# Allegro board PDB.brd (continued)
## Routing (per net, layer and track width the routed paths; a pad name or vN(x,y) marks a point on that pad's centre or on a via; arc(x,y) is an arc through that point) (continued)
PSU2_CPLD_PS_ON_N: length 194.6
  TOP w0.216: v1(152.27,91.38) 153.17,90.48 166.54,90.48 167.06,91 183.21,91 184.55,89.66 R59.2 184.55,87.9 CON1.1 ; L20.2 C25.1 17.89,111.37 19.53,113.02 102.13,113.02 v1(104.65,110.5)
  BOTTOM w0.216: v1(104.65,110.5) 105.16,110.5 110.49,105.17 110.49,104.66 111.99,103.16 111.99,101.92 111.66,101.59 111.66,100.26 111.43,100.03 111.43,97.78 111.48,97.73 111.48,97.71 115.13,94.07 115.13,89.32 119.17,85.28 136.69,85.28 137.59,86.18 144.72,86.18 147.56,89.03 149.92,89.03 v1(152.27,91.38)
PSU2_CPLD_PS_ON_R_N: length 30.9
  TOP w0.216: L20.1 17.53,105.76 13.17,101.4 1.82,101.4 1.42,101.01 1.42,95.75 1.65,95.52 3.22,95.52 J9.6
PSU2_GREEN_LED: length 64.6
  TOP w0.216: J6.12 64.52,26.63 64.52,28.21 63.73,28.99 R34.1 ; Q21.5 34.21,6.09 34.57,5.73 36.2,5.73 37.16,4.77 37.16,4 37.24,3.93 v1(37.24,3.88)
  BOTTOM w0.216: v1(37.24,3.88) 37.12,3.76 37.12,3.24 38.12,2.24 46.8,2.24 50.42,5.86 66.04,5.86 68.63,8.45 68.63,21.17 65.66,24.14 65.66,25.49 J6.12
PSU2_GREEN_LED_N: length 19.7
  TOP w0.216: R178.2 v1(24.66,5) 21.31,5 17.95,8.35 17.95,11.34 18.45,11.84 C151.1 L25.2
PSU2_GREEN_LED_R1_N: length 15.6
  TOP w0.216: L25.1 18.54,14.24 12.06,20.72 8.2,20.72 J10.6
PSU2_GREEN_LED_R_N: length 4
  TOP w0.216: R178.1 32.15,4.36 32.55,3.96 34.67,3.96 34.86,4.15 Q21.3
PSU2_PRESENT_N: length 170.9
  TOP w0.216: R66.1 v1(15.85,93.97)
  VCC1 w0.213: v1(15.85,93.97) 15.11,93.23 15.11,91.2 13.89,89.98 13.89,88.1 13.28,87.49 13.28,81.82 9.71,78.25 9.71,73.1 5.46,68.85 5.46,63.95 v1(6.15,63.26) ; J6.6 71.59,25.63 72.44,26.48 72.44,28.03 71.75,28.72 69.22,28.72 68.58,28.08 68.58,23.87 64.85,20.13 64.85,13.25 62.48,10.89 60.52,10.89 57.45,7.81 22.53,7.81 22,8.34 17.49,12.85 17.49,15.46 17.49,15.95 11.24,22.2 9.43,22.2 8.51,23.13 v1(8.51,23.43)
  BOTTOM w0.216: v1(6.15,63.26) 5.31,63.26 4.28,62.23 4.28,25.53 6.38,23.43 v1(8.51,23.43)
PSU2_PS_ON_BUF_N: length 91.8
  TOP w0.216: v1(106.3,107.08) 106.44,106.94 U1.4 ; U13.2 176.43,87.23 174.64,89.03 153.58,89.03 v1(152.55,90.06)
  BOTTOM w0.216: v1(152.55,90.06) 151.86,90.06 150.41,88.61 147.74,88.61 144.89,85.77 137.79,85.77 136.89,84.86 118.99,84.86 114.71,89.15 114.71,93.39 108.97,99.13 108.97,104.66 106.55,107.08 v1(106.3,107.08) 106.17,107.2 R107.2
PSU2_PS_ON_N: length 370
  TOP w0.216: R70.2 68.44,29.76 68.44,26.29 67.78,25.63 J6.10 ; R75.2 171.28,88.06 171.15,88.19 152.49,88.19 152,88.68 v1(151.99,88.68)
  VCC1 w0.213: v1(7.06,67.45) 7.49,67.45 10.96,70.92 10.96,76.61 15.96,81.6 16.81,81.6 17.32,82.1 17.32,87.65 18.8,89.13 18.8,91.53 20.95,93.68 20.95,101.68 24.26,104.99 68.02,104.99 69.22,106.19 75.23,106.19 76.89,104.53 79.7,104.53 84.5,99.73 95.75,99.73 96.49,100.47 96.49,102.88 97.69,104.08 99.36,104.08 v1(101.73,106.44)
  BOTTOM w0.216: v1(7.06,67.45) 6.55,67.96 4.65,67.96 1.77,65.08 1.77,24.49 5.93,20.32 11.16,20.32 20.12,11.36 20.12,9.06 23.6,5.58 30,5.58 34.18,1.4 47.15,1.4 50.77,5.02 66.39,5.02 69.47,8.1 69.47,21.52 67.52,23.47 J6.10 ; v1(151.99,88.68) 151.99,88.69 151.08,87.77 148.08,87.77 145.24,84.93 138.14,84.93 137.24,84.03 118.99,84.03 118.65,84.02 113.87,88.8 113.87,93.04 108.13,98.78 108.13,103.6 106.07,105.65 102.51,105.65 v1(101.73,106.44)
PSU2_PS_ON_R_N: length 4.5
  TOP w0.216: U13.7 172.4,87.23 R75.1 172.08,87.23 171.83,86.98 170.46,86.98 v3(169.93,87.52)
PSU2_VSENSE_DN: length 20.9
  BOTTOM w0.254: R194.1 82.77,99.3 C112.2 83.09,98.99 84.46,98.99 86.44,100.96 86.44,102.53 88.26,104.36 96.76,104.36 97.66,105.25 97.66,106.02 97.24,106.44 J21.4
PSU2_VSENSE_DP: length 23.6
  BOTTOM w0.254: R193.1 82.77,98.29 C112.1 83.09,98.6 84.62,98.6 86.82,100.8 86.82,102.38 88.42,103.98 96.92,103.98 98.04,105.09 98.04,106.84 97.1,107.78 J21.3
PSU2_YELLOW_LED: length 66.7
  TOP w0.216: v1(36.51,3.81) 36.68,3.98 36.68,4.66 36.03,5.31 34.48,5.31 34.21,5.04 Q21.2 ; J6.13 62.76,28.39 R31.1
  BOTTOM w0.216: J6.13 63.52,27.63 64.52,26.63 65.84,26.63 66.44,26.03 66.44,23.95 69.05,21.35 69.05,8.27 66.21,5.44 50.59,5.44 46.97,1.82 37.95,1.82 36.7,3.06 36.7,3.62 v1(36.51,3.81)
PSU2_YELLOW_LED_N: length 18.8
  TOP w0.216: L22.1 C148.1 19.61,11.84 20.07,11.38 20.07,9.95 19.41,9.29 19.41,7.51 21.23,5.68 v1(22.61,5.68) 31.02,5.68 R175.1
PSU2_YELLOW_LED_R1_N: length 20.6
  TOP w0.216: J10.5 5.8,18.15 5.8,20.21 6.72,21.13 12.24,21.13 19.56,13.82 L22.2
PSU2_YELLOW_LED_R_N: length 1.6
  TOP w0.216: Q21.6 33.12,6.01 R175.2
PSU3_ALERT_BUF_N: length 2.9
  TOP w0.216: v1(112.55,1.54) 112.42,1.67 R187.1
  BOTTOM w0.216: U23.4 113.25,2.82 112.55,2.12 v1(112.55,1.54)
PSU3_ALERT_N: length 28.4
  TOP w0.216: J7.11 91.7,1.28 109.22,1.28 109.78,1.84 110.18,1.84 v1(110.21,1.88) 110.3,1.88 110.75,2.33 112.84,2.33 113.39,1.78 R64.2
  BOTTOM w0.216: v1(110.21,1.88) 110.51,2.17 U23.2
PSU3_BLADE_EN_N: length 30.7
  TOP w0.216: J7.1 75.82,4.46 74.73,5.55 64.21,5.55 61.7,3.04 R74.1
PSU3_BLADE_EN_R_N: length 249.5
  TOP w0.216: U1.14 111.85,102.39 111.48,102.75 v1(111.47,102.75) ; R74.2 C30.1 48.57,4.78 v1(47.98,5.37)
  VCC1 w0.213: v1(106.35,108.4) 105.09,107.14 104.1,107.14 100.2,103.25 98.12,103.25 97.33,102.45 97.33,100.13 96.1,98.9 84.15,98.9 79.35,103.7 72.82,103.7 72.36,104.16 70.01,104.16 70,104.15 24.6,104.15 22.99,102.54 22.99,90.18 21.79,88.99 21.79,82.67 19.86,80.74 16.27,80.74 11.8,76.26 11.8,69.72 7.87,65.8 v1(7.06,65.8)
  BOTTOM w0.216: v1(106.35,108.4) 106.41,108.46 106.59,108.46 110.03,105.02 110.03,104.51 111.47,103.07 v1(111.47,102.75) 111.47,102.11 R112.2 ; v1(7.06,65.8) 5.31,65.8 3.02,63.51 3.02,25.01 6.46,21.58 11.68,21.58 22.36,10.89 22.36,8.59 24.05,6.9 46.84,6.9 47.98,5.76 v1(47.98,5.37)
PSU3_GREEN_LED: length 63.5
  TOP w0.216: Q22.5 27.66,2.12 27.99,2.45 38,2.45 40.39,4.84 45.47,4.84 45.87,5.24 R35.1 46.4,6.01 75.41,6.01 75.95,5.48 87.54,5.48 J7.12
PSU3_GREEN_LED_N: length 14.6
  TOP w0.216: L26.2 C150.1 17.07,11.84 17.53,11.38 17.53,8.18 22.5,3.22 v1(23.34,3.22) R179.2
PSU3_GREEN_LED_R1_N: length 11.4
  TOP w0.216: L26.1 17.02,15.17 13.5,18.68 9.26,18.68 J10.8
PSU3_GREEN_LED_R_N: length 1.4
  TOP w0.216: Q22.3 26.96,3.83 v1(26.41,3.83) 26.41,3.83 25.9,3.32 R179.1
PSU3_PRESENT_N: length 164.8
  TOP w0.216: v1(62.28,7.26) 65.03,7.26 65.15,7.38 82.08,7.38 82.53,6.93 J7.6 ; R67.1 v1(16.86,93.87)
  VCC1 w0.213: v1(6.6,64.66) 6.32,64.94 6.32,67.81 10.55,72.03 10.55,76.93 15.16,81.54 15.16,85.24 15.07,85.32 15.07,89.89 16.38,91.2 16.38,93.38 v1(16.86,93.87)
  BOTTOM w0.216: v1(6.6,64.66) 4.93,64.66 3.44,63.17 3.44,25.18 6.63,22 11.86,22 22.78,11.07 22.78,8.76 24.23,7.32 62.22,7.32 v1(62.28,7.26)
PSU3_PS_ON_BUF_N: length 86.5
  TOP w0.216: U1.5 v1(106.3,106.29) ; v1(152.53,89.19) 153.11,88.61 171.33,88.61 171.4,88.53 U13.5
  BOTTOM w0.216: v1(152.53,89.19) 151.59,89.19 150.58,88.19 147.91,88.19 145.06,85.35 137.97,85.35 137.07,84.44 118.82,84.44 114.29,88.98 114.29,93.21 108.55,98.95 108.55,104.04 v1(106.3,106.29) 106.2,106.19 R108.2
PSU3_PS_ON_N: length 189.3
  TOP w0.216: R76.2 178.06,89.45 153.9,89.45 v1(153.39,89.96) ; J7.10 88.03,7.96 R71.2 97.43,9.54 99.24,7.74 102.41,7.74 v1(102.57,7.58)
  BOTTOM w0.216: v1(153.39,89.96) 153.39,88.81 151.76,87.19 148.24,87.19 145.56,84.51 138.62,84.51 136.96,82.84 136.96,74.34 150.81,60.48 150.81,38.96 150.77,38.86 150.73,38.65 150.73,38.45 150.77,38.24 150.77,36.03 148.99,34.25 148.16,34.25 147.19,33.29 145.84,33.29 145.15,32.6 140.75,32.6 138.16,35.19 127.17,35.19 122.14,30.16 122.14,26.82 120.78,25.47 120.78,18.11 119.53,16.86 116.03,16.86 114.57,15.4 107.74,15.4 106.01,13.66 106.01,7.93 105.66,7.58 v1(102.57,7.58)
PSU3_PS_ON_R_N: length 3.5
  TOP w0.216: v3(180.34,89.04) 179.22,87.92 R76.1 178.75,87.88 U13.3
PSU3_VSENSE_DN: length 17.1
  BOTTOM w0.254: J21.6 94.29,107.25 89.96,107.25 85.67,102.96 85.67,101.82 84.72,100.87 83.12,100.87 C113.2 82.65,100.4 R196.1
PSU3_VSENSE_DP: length 17
  BOTTOM w0.254: J21.5 94.29,107.63 89.8,107.63 85.29,103.12 85.29,101.98 84.56,101.25 83.06,101.25 C113.1 82.77,101.54 R195.1
PSU3_YELLOW_LED: length 66.5
  TOP w0.216: v1(75.82,6.49) R32.1 45.87,6.73 45.47,7.13 42.04,7.13 37.78,2.87 28.17,2.87 27.66,3.38 Q22.2
  BOTTOM w0.216: J7.13 90.42,4.46 89.41,5.48 76.83,5.48 v1(75.82,6.49)
PSU3_YELLOW_LED_N: length 16.4
  TOP w0.216: R176.1 v1(24.31,2.2) 22.92,2.2 15.44,9.67 15.44,11.6 15.69,11.84 C149.1 L23.1
PSU3_YELLOW_LED_R1_N: length 10.6
  TOP w0.216: J10.7 9.66,18.18 13.42,18.18 16,15.59 L23.2
PSU3_YELLOW_LED_R_N: length 4
  TOP w0.216: Q22.6 28.32,1.87 28.32,1.28 28.12,1.08 26.24,1.08 v1(25.9,1.42) R176.2
PSU_ALERT_N: length 228.1
  TOP w0.216: v1(39.88,2.94) 41.02,1.79 69.47,1.79 69.74,2.07 R186.2 72.56,2.55 74.24,0.87 109.39,0.87 109.89,1.36 110.67,1.36 R187.2 ; R68.2 27.99,110.89 25.91,108.8 22.25,108.8 21.82,109.23 C133.1 L10.1 20.85,106.58 15.83,101.56 15.83,97.33 10.89,92.4 R188.2 ; R188.2 10.13,92.01 9.79,91.66 9.79,90.36 9.79,90.05 9.63,89.89 C130.1 v1(9.27,89.28) L5.1 ; R188.2 C116.1
  VCC1 w0.213: v1(4.93,67.17) 5.04,67.29 5.04,69.02 9.3,73.27 9.3,79.06 11.16,80.92 11.16,86.42 9.27,88.31 v1(9.27,89.28)
  BOTTOM w0.216: v1(4.93,67.17) 4.72,67.17 2.18,64.63 2.18,24.66 6.11,20.74 11.34,20.74 20.54,11.54 20.54,9.23 23.77,6 33.07,6 33.63,5.44 37.38,5.44 v1(39.88,2.94)
PSU_ALERT_R_N: length 3.3
  TOP w0.216: J8.11 10.24,85.89 9.27,86.86 L5.2
PSU_PRESENT_N: length 8.6
  TOP w0.216: L13.2 C144.1 14.96,90.5 14.96,92.07 15.22,92.33 R66.2 R67.2 C27.1 17.9,92.35 v1(18.65,92.34) R65.2
PSU_PRESENT_R_N: length 5.8
  TOP w0.216: L13.1 14.35,87.04 15.2,86.18 15.2,83.62 15.96,82.86 J8.6
PSU_PS_ON_AND_N: length 12.1
  TOP w0.216: CON1.2 182.35,85.76 180.72,87.39 v3(180.21,87.39) 180.09,87.39 179.26,86.56 R60.2 178.77,86.58 U13.1 175.57,86.58 174.27,87.88 U13.6
PSU_PS_ON_N: length 218
  TOP w0.216: R70.1 66.78,28.82 66.6,28.64 66.6,23.51 65.46,22.37 v1(65.15,22.37) ; L15.2 v1(10.54,89.2) C141.1 10.78,89.89 11.1,90.22 11.1,92.01 16.24,97.16 16.24,101.38 22.98,108.12 29,108.12 29.48,107.63 C29.1 R69.1 ; v1(63.88,7.89) 85.58,7.89 R71.1
  VCC1 w0.213: v1(10.59,78.22) 10.13,77.76 10.13,72.63 5.92,68.42 5.92,67.99 5.91,67.98 5.91,64.76 5.92,64.75 5.92,64.3 v1(6.17,64.05)
  BOTTOM w0.216: v1(10.54,89.2) 11.2,88.54 11.2,78.86 10.59,78.25 v1(10.59,78.22) ; v1(65.15,22.37) 65.01,22.23 65.01,8.02 64.89,7.89 v1(63.88,7.89) 62.09,7.89 61.94,7.74 24.4,7.74 23.27,8.87 23.27,11.18 12.03,22.41 6.8,22.41 3.86,25.36 3.86,62.7 5.21,64.05 v1(6.17,64.05)
PSU_PS_ON_R1_N: length 5.6
  TOP w0.216: J8.10 11.2,83.9 11.2,86.83 10.54,87.49 L15.1
PSU_VSENSE_DN: length 111.9
  TOP w0.254: R192.2 80.75,100.73 78.97,100.73 v1(78.72,100.48) 78.42,100.78 77.9,100.78 77.14,101.54 72.24,101.54 69.85,103.93 24.72,103.93 23.37,102.57 23.37,90.21 22.89,89.73 22.89,62.46 23.72,61.62 SHORT2.1
  VCC1 w0.254: v1(78.72,100.48) 79.02,100.78 80.18,100.78 80.7,100.26 80.7,99.18 80.47,98.96 80.04,98.96 v1(79.73,99.26)
  BOTTOM w0.254: R192.2 80.75,100.73 78.97,100.73 v1(78.72,100.48) ; v1(79.73,99.26) 80.01,98.99 80.77,98.99 R194.2
PSU_VSENSE_DP: length 114.7
  TOP w0.254: SHORT1.1 23.64,61.17 22.5,62.3 22.5,89.89 22.99,90.37 22.99,102.73 24.56,104.31 70.01,104.31 72.4,101.92 77.3,101.92 78.06,101.16 78.42,101.16 v1(78.72,101.46) 79.07,101.11 80.65,101.11 R191.2
  VCC1 w0.254: v1(79.73,98.28) 80.04,98.58 80.63,98.58 81.08,99.02 81.08,100.42 80.34,101.16 79.02,101.16 v1(78.72,101.46)
  BOTTOM w0.254: v1(78.72,101.46) 79.07,101.11 80.65,101.11 R191.2 ; v1(79.73,98.28) 80.06,98.6 80.77,98.6 R193.2
PU_I2C_PCA9546A_2_SCL: length 4.2
  TOP w0.216: v1(78.49,110) 77.83,109.34 U14.10
  BOTTOM w0.216: v1(78.49,110) 78.54,110 79.43,109.11 R98.2
PU_I2C_PCA9546A_2_SDA: length 4.1
  TOP w0.216: U14.9 76.57,110.09 v1(77.22,110.73)
  BOTTOM w0.216: R97.2 79.38,110.12 78.77,110.73 v1(77.22,110.73)
PU_I2C_PCA9546A_3_SCL: length 5.3
  TOP w0.216: U14.12 77.14,108.04 77.93,107.25 77.93,106.21 v1(78,106.14)
  BOTTOM w0.216: v1(78,106.14) 78.31,106.14 79.25,107.08 R100.2
PU_I2C_PCA9546A_3_SDA: length 3.8
  TOP w0.216: v1(78.44,108.35) 77.76,108.35 77.42,108.69 U14.11
  BOTTOM w0.216: v1(78.44,108.35) 79.23,108.35 R99.2
RISER3_OC_ALERT: length 11.1
  BOTTOM w0.216: Q13.5 140.36,23.61 139.73,22.98 R130.2 R132.1 139.3,21.99 138.81,21.99 138.61,21.78 v2(138.61,18.61) 139.05,18.17 R26.1 139.05,16.84 R160.1
RISER3_OC_ALERT_N: length 2.9
  BOTTOM w0.216: v2(144.42,13.02) 144.42,14.44 Q17.6 144.73,14.75 145.3,14.75
  BOTTOM w0.254: R159.2 145.3,14.75
RISER3_OC_ALERT_R: length 4.7
  BOTTOM w0.216: Q17.5 Q17.2 v2(141.12,15.25) 140.95,15.08 R160.2
RISER3_OC_ALERT_R1_N: length 6.3
  BOTTOM w0.216: Q17.3 142.69,16.21 142.91,16.43 145.25,16.43 145.25,16.44 145.48,16.44 R170.1 145.78,15.83 146.1,15.51 147.42,15.51 v2(147.84,15.93)
RISER3_OC_ALERT_R_N: length 153.3
  TOP w0.216: U1.17 v1(114.68,104.34)
  BOTTOM w0.216: v1(114.68,104.34) 116.83,104.34 118.87,102.3 144.03,102.3 150.57,95.76 152.74,95.76 154.27,97.28 157.34,97.28 158.09,96.53 158.09,89.92 152.75,84.58 150.91,84.58 148.97,82.64 148.97,66.62 154.78,60.81 154.78,53.15 154.78,52.81 162.1,45.48 162.1,36.74 154.76,29.4 151.71,29.4 150.6,28.28 150.6,20.23 151.41,19.42 151.41,15.53 149.91,14.04 147.73,14.04 147.55,14.21 R7.2 R159.1
RISER3_OC_CLEAR: length 113
  TOP w0.216: v1(106.4,104.34) U1.8 ; v1(145.9,24.73) 145.9,31.36 146.58,32.04 146.58,33.77 146.56,33.8 v1(146.56,33.8)
  BOTTOM w0.216: Q13.2 144.77,23.61 R17.1 144.89,23.62 145.9,24.63 v1(145.9,24.73) ; v1(106.4,104.34) 106.62,104.34 107.66,103.3 107.66,98.35 106.83,97.52 106.83,92.49 117.41,81.9 117.41,76.39 123.79,70.01 137.25,70.01 146.47,60.79 146.47,52.82 150.28,49.01 150.28,36.24 148.81,34.76 148.03,34.76 147.07,33.8 v1(146.56,33.8)
RISER4_OC_ALERT: length 7.1
  BOTTOM w0.216: R162.1 131.19,49.18 131.19,50.64 v2(130.71,51.12) 130.05,51.78 R27.1 R131.2 131.3,52.19 131.72,52.61 R133.1 132.28,52.61 132.82,53.15 Q14.5
RISER4_OC_ALERT_N: length 1.5
  BOTTOM w0.216: Q18.6 v4(126.7,49.81) 126.36,49.48 R161.2
RISER4_OC_ALERT_R: length 3.1
  BOTTOM w0.216: Q18.5 128.24,49.16 v4(128.37,49.04) 128.5,49.16 Q18.2 R162.2
RISER4_OC_ALERT_R1_N: length 4
  BOTTOM w0.216: v2(129.03,46.12) 129.77,46.12 R172.1 130.09,46.75 129.35,47.49 Q18.3
RISER4_OC_ALERT_R_N: length 113.5
  TOP w0.216: v1(104.72,101.87) 104.9,101.87 105.77,101.01 108.51,101.01 108.84,101.34 108.84,102.29 110.83,104.28 111.81,104.28 112.52,104.99 U1.18
  BOTTOM w0.216: v1(104.72,101.87) 104.65,101.8 104.65,98.44 105.15,97.94 105.15,91.79 115.74,81.21 115.74,75.7 123.1,68.33 136.55,68.33 144.79,60.1 144.79,47.67 142.45,45.33 126.49,45.33 126.36,45.46 R161.1 R8.2
RISER4_OC_CLEAR: length 72.1
  TOP w0.216: v1(104.96,103.14) 105.54,103.14 106.09,103.69 U1.9
  BOTTOM w0.216: v1(104.96,103.14) 104.27,103.14 104.14,103.01 104.14,98.13 104.73,97.54 104.73,91.62 115.32,81.03 115.32,75.52 122.92,67.92 130.09,67.92 133.25,64.76 133.25,60.21 135.36,58.1 135.36,55.49 136.25,54.59 R18.1 135.92,53.15 Q14.2
RISER5_OC_ALERT: length 7.5
  BOTTOM w0.216: R2.1 139.8,89.04 v2(139.55,88.79) R28.1 R144.2 138.28,89.77 R146.1 138.15,90.57 136.7,92.01 Q15.5
RISER5_OC_ALERT_N: length 2.7
  BOTTOM w0.216: R1.2 144.93,88.86 Q1.6 v2(146.56,88.9)
RISER5_OC_ALERT_R: length 6
  BOTTOM w0.216: R2.2 142.51,89.55 Q1.2 Q1.5 145.29,89.55 145.8,90.06 145.8,91.15 v2(146.3,91.66)
RISER5_OC_ALERT_R1_N: length 4.2
  BOTTOM w0.216: Q1.3 143.07,91.34 143.64,91.91 R5.1 144.08,92.15 v2(145.21,93.28)
RISER5_OC_ALERT_R_N: length 51.6
  TOP w0.216: v1(111.3,104.89) 112.06,105.65 113.53,105.65 U1.19
  BOTTOM w0.216: R1.1 R9.2 142.01,86.93 141.68,86.6 137.41,86.6 136.51,85.7 119.34,85.7 115.54,89.5 115.54,94.24 111.9,97.88 111.9,99.91 112.08,100.09 112.08,101.42 112.41,101.75 112.41,103.79 v1(111.3,104.89)
RISER5_OC_CLEAR: length 45.2
  TOP w0.216: U1.10 108.38,103.04 109.86,104.51 v1(109.86,107.51)
  BOTTOM w0.216: v1(109.86,107.51) 112.83,104.54 112.83,101.57 112.5,101.24 112.5,99.91 112.32,99.74 112.32,98.06 112.9,97.47 118.16,97.47 120.14,99.46 125.73,99.46 130.81,94.38 133.86,94.38 134.62,95.14 135.91,95.14 R19.1 136.7,94.56 Q15.2
RST_I2C_MUX_N: length 33.7
  TOP w0.216: v1(87.71,102.43) 87,103.14 84.33,103.14 83.67,103.79 R109.2 83.12,105.06 82.83,105.35 82.83,106.36 82.45,106.74 U14.3 ; U1.7 105.86,104.99 105.05,104.18 103.89,104.18 v1(103.2,103.49)
  BOTTOM w0.216: v1(87.71,102.43) 90.78,99.35 100.84,99.35 102.26,100.78 102.26,102.55 v1(103.2,103.49)
TEMP_SENSE_1_DN: length 205.5
  TOP w0.254: v1(91.26,101.27) 91.55,101.56 U2.3 ; v1(9.45,13.76) 9.75,13.46 10.33,13.46 C38.2 11.1,14.23 Q11.2
  VCC1 w0.254: v1(91.26,101.27) 90.92,101.61 89.94,101.61 89.36,102.19 89.36,110.48 87.48,112.36 73.69,112.36 72.62,111.29 68.39,111.29 66.88,112.8 43.46,112.8 43.13,112.47 35.43,112.47 35.42,112.47 34.17,112.47 34.17,112.47 27.07,112.47 25.11,110.5 22.38,110.5 13.56,101.69 3.17,101.69 1.55,100.07 1.55,95.26 1.72,95.1 1.72,15.01 3.25,13.48 9.16,13.48 v1(9.45,13.76)
TEMP_SENSE_1_DP: length 207.1
  TOP w0.254: Q11.1 12.85,13.28 Q11.3 11.64,13.28 11.18,12.82 10.59,12.82 C38.1 10.33,13.08 9.75,13.08 v1(9.45,12.78) ; v1(91.26,102.25) 91.45,102.06 U2.2
  VCC1 w0.254: v1(9.45,12.78) 9.13,13.1 3.09,13.1 1.34,14.85 1.34,94.94 1.17,95.11 1.17,100.22 3.02,102.07 13.41,102.07 22.22,110.89 24.95,110.89 26.91,112.85 34.01,112.85 34.01,112.85 35.58,112.85 35.59,112.85 42.97,112.85 43.31,113.18 67.04,113.18 68.55,111.67 72.46,111.67 73.53,112.74 87.64,112.74 89.74,110.64 89.74,102.35 90.09,102 91,102 v1(91.26,102.25)
TEMP_SENSE_2_DN: length 102.3
  TOP w0.254: U2.5 93.92,100.56 93.98,100.62 94.25,100.62 95.93,98.95 102.46,98.95 105.63,95.77 107.32,95.77 v1(107.62,95.47) ; v1(147.7,61.28) 148,61.58 152.52,61.58 159.09,55.02 167.43,55.02 167.72,54.73 C37.2 168.58,54.73 Q10.2
  BOTTOM w0.254: v1(107.62,95.47) 108,95.85 108.74,95.85 109.27,95.32 109.27,91.45 118.41,82.31 118.41,76.81 124.21,71.01 137.66,71.01 147.07,61.6 147.39,61.6 v1(147.7,61.28)
TEMP_SENSE_2_DP: length 104.2
  TOP w0.254: U2.4 93.92,101.06 93.98,101 94.41,101 96.09,99.33 102.62,99.33 105.79,96.15 107.32,96.15 v1(107.62,96.45) ; v1(147.7,62.27) 148,61.97 152.68,61.97 159.25,55.4 167.59,55.4 167.72,55.53 C37.1 169.39,55.53 Q10.1 170.59,55.68 Q10.3
  BOTTOM w0.254: v1(107.62,96.45) 107.84,96.23 108.9,96.23 109.65,95.47 109.65,91.61 118.79,82.47 118.79,76.96 124.36,71.39 137.82,71.39 147.23,61.98 147.41,61.98 v1(147.7,62.27)
UNNAMED_9_AT24C64D_I33_WP: length 5.8
  TOP w0.216: v3(157.23,93.5) 157.86,92.87 160.25,92.87 160.52,93.14 R117.1 U3.7
UNNAMED_10_RES_I2_A: length 3.3
  BOTTOM w0.216: R136.1 145.23,17.8 144.92,17.49 v2(144.81,17.49) 144.61,17.49 143.87,18.24 U5.3
UNNAMED_10_RES_I18_B: length 3.1
  BOTTOM w0.216: R132.2 139.32,20.08 v2(139.45,19.95) 139.86,19.54 U5.6
UNNAMED_10_RES_I30_A: length 2.1
  BOTTOM w0.216: R137.1 135.96,47.44 v4(135.59,47.44) 135.24,47.78 U7.3
UNNAMED_10_RES_I40_B: length 3.5
  BOTTOM w0.216: R133.2 v2(132.08,50.56) 132.08,50.43 131.7,50.05 131.7,49.29 131.91,49.08 U7.6
UNNAMED_11_RES_I2_A: length 3.9
  BOTTOM w0.216: v2(143.61,96.51) 142.98,95.89 R150.1 142.08,95.84 U9.3
UNNAMED_11_RES_I13_B: length 6.3
  BOTTOM w0.216: R146.2 139.08,90.58 140.05,91.55 U9.6 140.78,91.92 141.17,92.32 142.24,92.32 143.74,93.82 v2(143.84,93.82)
UNNAMED_11_RES_I20_A: length 3.1
  BOTTOM w0.216: R151.1 181.08,84.47 v2(180.09,84.47) 180.09,84.06 180.76,83.39 U11.3
UNNAMED_11_RES_I26_B: length 4.9
  BOTTOM w0.216: U11.6 183.97,82.01 184.09,81.87 184.09,81.21 184.3,80.99 185.37,80.99 185.5,81.12 185.75,81.12 v2(185.83,81.04) 185.83,80.42 R147.2
UNNAMED_12_NPN_I60_B: length 43
  TOP w0.216: v1(105.6,27.51) 106.09,27.51 PR1047.2
  BOTTOM w0.254: v1(105.6,27.51) 105.17,27.51 104.22,28.46 104.22,29.45 98.76,34.91 97.14,34.91 93.55,38.51 93.55,56.17 v2(93.95,56.58) 94.36,56.99 PQ109.3 94.36,61.91 PQ109.1
UNNAMED_12_NPN_I60_E: length 41.9
  TOP w0.216: v1(105.61,28.23) 106.23,28.23 PR1046.2
  BOTTOM w0.254: v1(105.61,28.23) 105.11,28.23 104.67,28.67 104.67,29.64 98.94,35.37 97.33,35.37 94.01,38.7 94.01,55.69 94.82,56.5 94.82,59.53 95.25,59.96 95.25,62.8 PQ109.2
UNNAMED_19_CAP_I128_A: length 1.5
  TOP w0.381: PR27.2 173.81,34.45 v1(174.29,34.94) 173.81,35.43 PC28.1
UNNAMED_23_CAP_I5_A: length 1.4
  TOP w0.508: C166.1 R234.2
UNNAMED_23_CAP_I8_A: length 1.3
  BOTTOM w0.508: R236.2 C168.1
UNNAMED_23_CAP_I12_A: length 1.6
  BOTTOM w0.508: R238.2 27.25,66.27 C170.1
UNNAMED_23_CAP_I17_A: length 1.8
  TOP w0.508: R244.2 v1(130.84,100.6) C176.1
UNNAMED_23_CAP_I20_A: length 1.5
  BOTTOM w0.508: C174.1 176.08,72.15 R242.2
UNNAMED_23_CAP_I24_A: length 1.4
  BOTTOM w0.381: R240.2 54.21,24.02 C172.1
UNNAMED_23_CAP_I32_A: length 1.8
  TOP w0.381: C175.1 v1(144.83,75.96) R243.2
UNNAMED_23_CAP_I40_A: length 1.3
  TOP w0.381: R239.2 C171.1
UNNAMED_23_CAP_I48_A: length 1.3
  BOTTOM w0.508: C167.1 R235.2
UNNAMED_23_CAP_I52_A: length 1.8
  TOP w0.381: C178.1 176.99,48.34 v1(177.62,48.34)
  TOP w0.508: v1(177.62,48.34) R57.2
UNNAMED_23_CAP_I56_A: length 1.5
  BOTTOM w0.381: R221.2 155.39,14.49 C191.1
UNNAMED_23_CAP_I60_A: length 1.5
  TOP w0.381: R222.2 160.23,53.16 C192.1
UNNAMED_23_CAP_I64_A: length 2
  TOP w0.508: R223.2 168.97,85.23 v1(169.65,85.23) C193.1
UNNAMED_214_ADM1172_I37_SENSE: length 3.5
  TOP w0.254: R155.2 105.15,9.44 105.31,9.29 v1(105.31,8.9) 105.31,8.73 105.03,8.45 C110.2 104.5,8.23 U20.7
UNNAMED_214_ADM1172_I37_VCC: length 5.6
  TOP w0.254: U20.8 103.85,7.56 103.72,7.69 103.25,7.69 102.39,8.55 C108.1 103.05,8.83 v1(103.25,8.63) 103.43,8.45 C110.1 103.92,9.34 R154.2
UNNAMED_214_CAP_I27_A: length 3.3
  TOP w0.381: C105.1 115.62,3.49 115.37,3.24 v1(114.96,3.24) 114.48,3.72 R50.2
VR_P3V3_CB_BT: length 2.5
  TOP w0.254: PU113.14 168.99,104.98 v1(168.83,104.83)
  BOTTOM w0.508: PC1828.1 168.43,105.23 v1(168.83,104.83)
VR_P3V3_CB_PVIN:
  vias: v1(162.69,101.61) v1(163.7,101.49) v1(164.59,101.5) v1(164.97,102.34) v1(165.33,104.5) v1(165.38,101.35) v1(165.68,105.92) v1(166.34,104.52) v2(161.14,102.15)
VR_P3V3_CB_SW: length 1.5
  BOTTOM w0.508: v1(166.95,108) 167.54,107.41 PC1828.2
VR_P3V3_STBY_BT: length 3.5
  TOP w0.254: v1(161.35,21.09) 161.2,20.94 PU33.14
  BOTTOM w0.381: v1(161.35,21.09) 161.09,20.83 v2(161.09,20.31) 162.1,20.31 PC828.1
VR_P3V3_STBY_PVIN: length 11.9
  VCC1 w0.305: v1(161.75,15.58) 161.93,15.76 161.93,19.83 162.56,20.46 162.56,22.16 163.17,22.77 167.02,22.77 v1(167.22,22.97)
  vias: v1(163.71,21.83) v1(163.79,24.37) v1(164.04,21.14) v1(164.58,20.05) v1(164.98,20.96)
VR_P3V3_STBY_SW: length 1.6
  BOTTOM w0.508: PC828.2 162.48,18.67 v1(163.24,17.92)

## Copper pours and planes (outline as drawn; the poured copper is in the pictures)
GND on TOP (solid shape): 22.99,16.78 22.99,15.51 22.73,15.25 21.21,15.25 18.8,17.67 18.8,19.06 19.18,19.45 20.32,19.45
GND on TOP (solid shape): 27.69,78.75 27.69,76.6 27.3,76.21 24.51,76.21 24.26,76.47 24.26,78.88 24.51,79.14 27.3,79.14
GND on TOP (solid shape): 27.69,71.64 27.69,69.48 27.3,69.1 24.51,69.1 24.26,69.36 24.26,71.77 24.51,72.02 27.3,72.02
GND on TOP (solid shape): 52.7,27.45 52.7,25.41 52.58,25.29 48.9,25.29 48.51,25.67 48.51,27.19 48.9,27.57 52.58,27.57
GND on TOP (solid shape): 54.1,66.82 54.1,64.66 53.72,64.28 50.04,64.28 49.66,64.66 49.66,67.07 49.91,67.32 53.59,67.32
GND on TOP (solid shape): 62.61,90.57 62.61,87.14 62.1,86.63 60.71,86.63 60.45,86.88 60.45,90.57 60.83,90.95 62.23,90.95
GND on TOP (solid shape): 72.14,90.57 72.14,87.14 71.63,86.63 70.23,86.63 69.98,86.88 69.98,90.57 70.36,90.95 71.75,90.95
GND on TOP (solid shape): 74.93,48.78 74.93,46.5 74.42,45.99 62.48,45.99 61.98,46.5 61.98,48.78 62.48,49.29 74.42,49.29
GND on TOP (solid shape): 75.18,66.82 75.18,64.66 74.8,64.28 65.02,64.28 64.39,64.91 64.39,66.69 65.02,67.32 74.68,67.32
GND on TOP (solid shape): 76.83,36.21 76.83,32.27 76.58,32.02 73.03,32.02 72.39,32.65 72.39,35.83 73.15,36.59 76.45,36.59
GND on TOP (solid shape): 84.14,11.89 84.14,8.71 83.82,8.4 82.17,8.4 81.92,8.65 81.92,11.95 82.38,12.42 83.61,12.42
GND on TOP (solid shape): 94.26,35.8 94.26,32.43 93.98,32.15 90.81,32.15 90.55,32.4 90.55,35.57 90.91,35.93 94.13,35.93
GND on TOP (solid shape): 98.55,35.7 98.55,33.67 98.42,33.54 97.16,33.54 97.03,33.67 97.03,35.7 97.16,35.83 98.42,35.83
GND on TOP (solid shape): 111.02,81.24 111.02,80.38 110.74,80.1 106.68,80.1 106.43,80.35 106.43,81.29 106.68,81.55 110.72,81.55
GND on TOP (solid shape): 111.02,70.17 111.02,69.31 110.74,69.03 106.68,69.03 106.43,69.28 106.43,70.22 106.68,70.47 110.72,70.47
GND on TOP (solid shape): 111.02,58.84 111.02,57.98 110.74,57.7 106.68,57.7 106.43,57.95 106.43,58.89 106.68,59.15 110.72,59.15
GND on TOP (solid shape): 111.02,50.31 111.02,49.44 110.74,49.16 106.68,49.16 106.43,49.42 106.43,50.36 106.68,50.61 110.72,50.61
GND on TOP (solid shape): 111.02,41.39 111.02,40.53 110.74,40.25 106.68,40.25 106.43,40.5 106.43,41.44 106.68,41.7 110.72,41.7
GND on TOP (solid shape): 119,112.79 119,109.11 118.49,108.6 117.22,108.6 116.84,108.98 116.84,112.66 117.09,112.92 118.87,112.92
GND on TOP (solid shape): 122.3,15.25 122.3,14.11 121.41,13.22 119,13.22 118.75,13.48 118.75,15.38 118.87,15.51 122.05,15.51
GND on TOP (solid shape): 129.16,76.34 129.16,75.58 128.78,75.2 125.48,75.2 125.35,75.33 125.35,76.47 125.46,76.58 128.92,76.58
GND on TOP (solid shape): 133.22,37.35 133.22,36.08 132.97,35.83 128.14,35.83 127.89,36.08 127.89,37.1 128.4,37.61 132.97,37.61
GND on TOP (solid shape): 134.24,97.68 134.24,94.5 133.86,94.12 131.95,94.12 131.44,94.63 131.44,97.68 131.7,97.93 133.99,97.93
GND on TOP (solid shape): 142.62,61.86 142.62,57.93 142.24,57.55 140.08,57.55 139.83,57.8 139.83,61.99 140.34,62.5 141.99,62.5
GND on TOP (solid shape): 148.44,112.17 148.44,104.09 148.39,104.04 147.17,104.04 147.09,104.12 147.09,112.12 147.24,112.27 148.33,112.27
GND on TOP (solid shape): 151.89,27.83 151.89,24.65 151.76,24.53 149.61,24.53 149.22,24.91 149.22,27.57 149.73,28.08 151.64,28.08
GND on TOP (solid shape): 152.27,60.34 152.27,57.55 151.89,57.16 149.86,57.16 149.61,57.42 149.61,60.47 149.83,60.69 151.92,60.69
GND on TOP (solid shape): 153.8,17.54 153.8,14.49 153.42,14.11 151.92,14.11 151.79,14.24 151.79,17.67 151.92,17.79 153.54,17.79
GND on TOP (solid shape): 160.96,25.38 160.96,22.02 160.72,21.78 159.3,21.78 159.09,21.99 159.09,25.43 159.27,25.61 160.73,25.61
GND on TOP (solid shape): 162.1,59.75 162.1,56.58 161.81,56.29 159.72,56.29 159.5,56.51 159.5,59.94 159.81,60.26 161.59,60.26
GND on TOP (solid shape): 164.08,99.9 164.08,98.88 163.88,98.68 162.44,98.68 162.25,98.87 162.25,100.36 162.3,100.41 163.57,100.41
GND on TOP (solid shape): 169.1,25.59 169.1,24.11 168.67,23.68 165.9,23.68 165.36,24.22 165.36,25.56 165.49,25.69 169,25.69
GND on TOP (solid shape): 175.39,13.48 175.39,10.94 174.5,10.05 173.35,10.05 173.1,10.3 173.1,13.6 173.23,13.73 175.13,13.73
GND on TOP (solid shape): 182.88,49.04 182.88,47.77 182.75,47.64 180.09,47.64 179.96,47.77 179.96,49.04 180.09,49.16 182.75,49.16
GND on TOP (solid shape): 188.59,36.72 188.59,29.86 187.71,28.97 185.8,28.97 185.55,29.22 185.55,36.84 185.8,37.1 188.21,37.1
GND on TOP (solid shape): 148.59,58.43 148.59,56.91 147.96,56.28 146.69,56.28 145.92,57.04 144.91,57.04 144.65,57.29 144.65,58.56 145.03,58.94 148.08,58.94
GND on TOP (solid shape): 156.03,101.93 156.03,99.92 155.42,99.31 153.9,99.31 153.8,99.42 153.8,100.53 154.1,100.84 154.1,101.73 154.53,102.16 155.8,102.16
GND on TOP (solid shape): 177.55,83.71 177.55,80.53 177.16,80.15 175.9,80.15 175.64,80.41 175.64,83.81 175.64,83.96 175.77,84.09 177.16,84.09
GND on TOP (solid shape): 105.22,94.44 109.28,94.44 109.98,95.14 111.25,95.14 111.76,94.63 111.76,91.58 111.63,91.45 103,91.45 102.49,91.96 102.49,94.88 103,95.39 104.27,95.39
GND on TOP (solid shape): 107.06,30.75 107.06,29.1 106.81,28.84 105.41,28.84 105.03,28.46 105.03,28.08 104.65,27.7 102.49,27.7 101.98,28.21 101.98,30.88 102.23,31.13 106.68,31.13
GND on TOP (solid shape): 170.59,34.05 171.55,34.05 171.55,34.05 171.83,34.05 171.96,33.92 171.96,32.27 171.83,32.15 170.43,32.15 170.31,32.27 170.31,33.92 170.43,34.05
GND on TOP (solid shape): 170.04,104.05 170.8,104.05 171.03,104.05 171.04,104.05 171.04,103.09 171.09,103.04 171.09,100.48 170.92,100.31 169.22,100.31 168.91,100.61 168.91,103.92 169.14,104.14 169.95,104.14
GND on TOP (solid shape): 152.02,97.68 152.02,94.63 151.83,94.44 151.64,94.44 151.51,94.43 151.39,94.38 151.37,94.38 148.97,94.38 148.72,94.63 148.72,97.68 148.84,97.8 151.89,97.8
GND on TOP (solid shape): 172.76,25.69 172.76,22.46 172.45,22.16 172.45,21.27 172.02,20.84 171.31,20.84 171.18,20.96 171.18,21.96 171.31,22.08 171.31,25.54 171.1,25.74 171.1,25.99 171.23,26.12 172.32,26.12
GND on TOP (solid shape): 178.09,20.02 178.09,14.26 177.94,14.11 176.54,14.11 176.44,14.21 176.44,15.71 176.24,15.91 176.24,16.14 176.44,16.34 176.44,17.84 176.21,18.07 176.21,18.4 176.44,18.63 176.44,19.8 176.74,20.1 178.01,20.1
GND on TOP (solid shape): 165.81,111.18 167.18,111.18 167.44,110.92 167.44,110.76 167.72,110.48 167.72,110.33 168.12,109.92 168.12,109.2 165.43,109.2 165.2,109.42 165.2,109.78 164.67,110.31 164.36,110.31 163.78,110.9 163.78,111.3 164.29,111.81 165.18,111.81
GND on TOP (solid shape): 20.05,22.03 20.05,20.75 19.61,20.31 18.83,20.31 18.81,20.32 18.65,20.35 18.49,20.32 18.47,20.31 16.18,20.31 16.05,20.44 16.05,22.47 16.18,22.6 19.48,22.6
GND on TOP (solid shape): 164.98,16.49 164.98,16.14 164.97,16.13 164.97,16.02 165.38,15.6 165.82,15.6 166.41,15.02 166.41,14.61 165.9,14.11 165.01,14.11 164.99,14.13 164.57,14.13 163.96,14.74 162.65,14.74 162.25,15.13 162.25,15.59 162.09,15.76 162.06,15.8 162.06,16.72 164.75,16.72
GND on TOP (solid shape): outline of 344 points within 1,103 16,113
GND on TOP (solid shape): outline of 344 points within 87,86 102,96
GND on TOP (solid shape): outline of 344 points within 87,20 102,30
GND on TOP (solid shape): outline of 344 points within 174,50 189,60
GND on TOP (solid shape): outline of 344 points within 174,1 189,11
GND on BOTTOM (solid shape): 148.46,110.52 148.46,104.3 148.21,104.04 147.19,104.04 147.07,104.17 147.07,110.52 147.32,110.77 148.21,110.77
GND on BOTTOM (solid shape): 160.96,25.23 160.96,21.87 160.72,21.62 159.14,21.62 159.09,21.68 159.09,25.28 159.27,25.46 160.73,25.46
GND on BOTTOM (solid shape): 164.08,100.41 164.08,99.39 163.88,99.19 162.25,99.19 162.13,99.31 162.13,100.81 162.23,100.91 163.58,100.91
GND on BOTTOM (solid shape): 173.61,50.56 173.61,46.24 173.48,46.12 171.32,46.12 171.2,46.24 171.2,50.56 171.58,50.94 173.23,50.94
GND on BOTTOM (solid shape): 188.59,36.72 188.59,30.75 188.09,30.24 186.44,30.24 185.55,31.13 185.55,36.84 185.8,37.1 188.21,37.1
GND on BOTTOM (solid shape): 171.09,104.24 171.09,100.64 171.15,100.58 171.15,99.94 171.02,99.81 169.32,99.81 169.23,99.9 169.23,104.05 169.47,104.29 171.04,104.29
GND on BOTTOM (solid shape): 116.59,14.11 116.59,10.81 116.33,10.56 115.06,10.56 114.94,10.68 114.94,11.57 114.05,12.46 108.08,12.46 107.7,12.84 107.7,13.98 108.08,14.37 116.33,14.37
GND on BOTTOM (solid shape): 116.38,33.21 116.38,33.01 116.18,32.81 115.45,32.81 115.38,32.8 115.29,32.78 114.68,32.78 114.3,32.4 114.3,32.02 113.54,31.26 111.63,31.26 111.61,31.28 111.61,32.76 111.6,32.91 113.54,32.91 114.05,33.42 116.17,33.42
GND on BOTTOM (solid shape): 166.1,111.21 167.14,111.21 167.64,110.72 167.64,109.12 167.28,108.76 166.55,108.76 166.34,108.56 165.15,108.56 163.91,107.32 162.99,107.32 162.58,106.91 162.58,103.86 162.19,103.47 160.49,103.47 159.54,102.52 158.09,102.52 156.87,101.3 156.87,99.75 156.31,99.19 154.15,99.19 154.05,99.29 154.05,103.66 154.71,104.32 154.71,110.06 156.5,111.85 165.47,111.85
GND on BOTTOM (solid shape): 172.5,25.82 172.5,22.31 171.75,21.56 171.75,21 171.64,20.89 171.64,19.01 172.04,18.6 175.27,18.6 175.55,18.88 175.55,19.74 175.6,19.8 177.45,19.8 177.93,19.32 177.93,15.64 177.4,15.11 173.35,15.11 172.31,14.07 164.72,14.07 164.08,14.7 163.04,14.7 162.55,15.2 162.55,16.8 162.9,17.15 163.64,17.15 163.84,17.36 165.03,17.36 166.28,18.6 167.19,18.6 167.64,19.05 167.64,23.24 167.22,23.66 165.9,23.66 165.72,23.83 165.72,24.75 166.08,25.1 168.26,25.1 168.39,24.98 168.39,24.42 168.85,23.96 170.64,23.96 171,24.32 171,25.97 171.18,26.15 172.17,26.15
GND on BOTTOM (solid shape): outline of 344 points within 1,103 16,113
GND on BOTTOM (solid shape): outline of 344 points within 87,86 102,96
GND on BOTTOM (solid shape): outline of 344 points within 87,20 102,30
GND on BOTTOM (solid shape): outline of 344 points within 174,50 189,60
GND on BOTTOM (solid shape): outline of 344 points within 174,1 189,11
GND on GND (solid shape): outline of 56800 points within 0.51,0.51 189.49,113.49
GND on GND1 (solid shape): outline of 57884 points within 0.51,0.51 189.49,113.49
P3V3_CB on TOP (solid shape): outline of 113 points within 135.38,97.95 147.57,112.73
P3V3_CB_AGND on BOTTOM (solid shape): 171.5,109.4 171.5,108.56 172.06,108 172.06,107.67 171.86,107.47 170.61,107.47 170.6,107.46 170.55,107.46 170.41,107.32 170.41,106.59 170.1,106.29 169.39,106.29 169.24,106.44 169.24,108.46 169.44,108.66 170.26,108.66 170.38,108.79 170.38,109.22 170.61,109.45 171.45,109.45
P3V3_CB_OUT on TOP (solid shape): 155.07,110.25 155.07,105.04 153.67,103.65 153.67,101.11 153.29,100.73 153.29,98.82 152.8,98.33 149.1,98.33 148.92,98.51 148.92,112.07 149.12,112.27 153.05,112.27
P3V3_CB_OUT on BOTTOM (solid shape): 153.29,109.11 153.29,99.33 153.17,99.21 149.78,99.21 149.5,99.49 149.5,100.46 149.27,100.69 148.41,100.69 148.26,100.84 148.26,103.07 148.92,103.73 148.92,110.39 149.17,110.64 151.75,110.64
P3V3_RISER4 on TOP (solid shape): outline of 170 points within 175.64,28.97 185.23,40.78
P3V3_RISER4 on BOTTOM (solid shape): outline of 170 points within 175.64,30.24 185.23,40.78
P3V3_STBY on TOP (solid shape): 181.74,31.76 181.74,22.24 180.09,20.59 177.42,20.59 176.97,21.03 176.97,26.24 176.15,27.07 159.38,27.07 158.88,27.57 158.88,31.13 159.39,31.64 172.97,31.64 174.75,33.42 180.09,33.42
P3V3_STBY on VCC (solid shape): outline of 20388 points within 1.27,12.71 188.34,112.92
P3V3_STBY_AGND on BOTTOM (solid shape): 161.51,17.79 161.72,17.79 161.85,17.67 161.85,17.06 161.75,16.96 160.93,16.96 160.63,17.26 159.93,17.26 159.8,17.13 159.8,16.84 159.43,16.47 158.74,16.47 158.68,16.52 158.68,17.36 158.13,17.92 158.13,18.25 158.33,18.45 160.86,18.45
P3V3_STBY_OUT on TOP (solid shape): 176.02,25.56 176.02,18.68 175.77,18.43 175.77,18.05 176.02,17.79 176.02,16.4 175.77,16.14 175.77,15.76 176.02,15.51 176.02,14.24 175.89,14.11 172.93,14.11 171.46,15.58 171.46,19.54 172.76,20.84 172.76,21.88 173.14,22.26 173.14,25.38 173.14,25.39 173.14,26.08 173.43,26.37 175.21,26.37
P3V3_STBY_OUT on BOTTOM (solid shape): 175.18,26.04 175.18,24.3 175.55,23.94 176.49,23.94 177.02,23.4 177.02,20.53 176.87,20.38 175.55,20.38 175.25,20.08 175.25,19.26 175.12,19.14 172.07,19.14 172.03,19.17 172.03,20.57 172.2,20.74 172.2,21.32 173.06,22.18 173.06,26.26 173.21,26.41 174.8,26.41
P12V_FAN on TOP (solid shape): outline of 954 points within 156.97,60.21 188.52,74.82
P12V_FAN on BOTTOM (solid shape): outline of 604 points within 156.59,62.75 188.72,73.67
P12V_FAN on VCC1 (solid shape): outline of 1336 points within 156.97,55.39 188.98,76.21
P12V_PSU on TOP (solid shape): outline of 1106 points within 10.41,11.06 103.68,99.58
P12V_PSU on BOTTOM (solid shape): outline of 2417 points within 10.41,11.06 103.63,99.58
P12V_PSU on VCC (solid shape): outline of 3279 points within 11.18,8.02 90.55,99.58
P12V_PSU on VCC1 (solid shape): outline of 3016 points within 12.57,11.83 88.39,99.58
P12V_RISER3 on TOP (solid shape): outline of 2049 points within 116.68,1.27 168.15,24.14
P12V_RISER3 on BOTTOM (solid shape): outline of 1415 points within 119.51,1.27 171.7,23.26
P12V_RISER3 on VCC1 (solid shape): outline of 3827 points within 112.78,1.27 172.56,24.08
P12V_RISER4 on TOP (solid shape): outline of 2596 points within 119.13,35.83 184.15,56.02
P12V_RISER4 on VCC1 (solid shape): outline of 5055 points within 119.13,28.08 184.15,55.89
P12V_RISER5 on TOP (solid shape): outline of 1617 points within 122.56,75.2 168.4,93.42
P12V_RISER5 on VCC1 (solid shape): outline of 3977 points within 122.56,76.81 181.61,96.28
P12V_STBY on TOP (solid shape): 113.59,8.7 113.59,3.88 113.46,3.75 109.4,3.75 109.27,3.88 109.27,8.45 109.78,8.96 113.33,8.96
P12V_STBY on TOP (solid shape): 170.93,25.46 170.93,23.25 170.75,23.07 169.71,23.07 169.44,23.34 169.44,25.57 169.63,25.76 170.62,25.76
P12V_STBY on TOP (solid shape): 172.47,13.48 172.47,12.21 172.72,11.95 172.72,9.67 171.83,8.78 168.78,8.78 168.28,8.27 168.28,7.72 168.26,7.62 168.25,7.53 168.25,7.36 167.77,6.87 166.5,6.87 165.86,7.51 165.86,12.46 167.39,13.98 171.96,13.98
P12V_STBY on TOP (solid shape): 160.07,101.04 160.07,100 159.61,99.54 159.61,99.39 159.6,99.38 159.53,99.12 159.57,98.86 159.59,98.81 159.51,98.73 157.68,98.73 157.38,99.04 157.38,100.95 157.64,101.22 159.89,101.22
P12V_STBY on TOP (solid shape): 175.39,83.71 175.39,80.28 175.01,79.9 172.72,79.9 172.68,79.94 172.68,81.65 171.94,82.38 171.21,81.65 171.21,81.04 169.16,81.04 168.91,81.29 168.91,83.71 169.54,84.34 174.75,84.34
P12V_STBY on BOTTOM (solid shape): 114.43,11.44 114.43,5.98 113.67,5.22 113,5.22 112.98,5.22 111.56,5.22 111.53,5.22 109.73,5.22 109.47,5.48 109.47,7.76 107.95,9.29 107.95,11.7 108.2,11.95 113.92,11.95
P12V_STBY on BOTTOM (solid shape): 170.03,50.94 170.13,50.9 170.18,50.8 170.36,50.52 170.7,50.48 170.75,50.5 170.81,50.43 170.81,45.48 170.43,45.1 170.43,41.67 170.18,41.42 168.28,41.42 168.02,41.67 168.02,49.27 168.06,49.37 168.17,49.42 168.53,49.8 168.17,50.18 168.06,50.23 168.02,50.33 168.02,50.56 168.4,50.94
P12V_STBY on VCC (solid shape): outline of 11748 points within 109.47,1.16 187.96,103.52
P12V_SW_PSU on TOP (solid shape): outline of 687 points within 99.26,25.41 155.51,112.79
P12V_SW_PSU on BOTTOM (solid shape): outline of 815 points within 101.47,36.97 131.06,83.07
P12V_SW_PSU on VCC (solid shape): outline of 8996 points within 99.44,25.41 155.19,98.95
P12V_SW_PSU on VCC1 (solid shape): outline of 4158 points within 99.44,26.49 155.51,112.16
HS_P12V_RSEN on TOP (solid shape): outline of 106 points within 89.9,37.61 98.81,83.45
HS_P12V_RSEN on VCC (solid shape): 98.81,83.2 98.81,37.99 98.42,37.61 90.42,37.61 89.9,38.13 89.9,44.21 90.04,44.35 90.04,45.08 89.9,45.23 89.9,51.07 90.04,51.21 90.04,51.81 89.9,51.96 89.9,57.93 90.04,58.07 90.04,58.8 89.9,58.94 89.9,64.66 90.04,64.8 90.04,65.53 89.9,65.67 89.9,71.63 90.17,71.9 90.17,72.28 90.15,72.28 89.9,72.53 89.9,73.17 89.9,73.17 89.9,73.94 89.9,73.94 89.9,76.09 89.91,76.1 89.9,76.1 89.9,78.48 90.17,78.75 90.17,79.14 90.15,79.14 89.9,79.39 89.9,83.18 90.17,83.45 98.55,83.45
HS_P12V_RSEN on VCC1 (solid shape): 98.81,83.2 98.81,37.99 98.42,37.61 90.42,37.61 89.9,38.13 89.9,41.04 89.9,44.08 90.04,44.23 90.04,44.96 89.9,45.1 89.9,50.92 90.04,51.07 90.04,51.96 89.9,52.1 89.9,57.91 90.04,58.05 90.04,58.43 89.9,58.58 89.9,64.77 90.04,64.91 90.04,65.42 89.9,65.56 89.9,71.64 90.04,71.79 90.04,72.28 89.9,72.42 89.9,78.5 90.04,78.64 90.04,79.26 89.9,79.41 89.9,83.18 90.17,83.45 98.55,83.45
HSC_P12V_AGND on TOP (solid shape): 113.79,22.24 113.67,22.11 110.36,22.11 110.36,25.54 113.79,25.54
HSC_P12V_AGND on BOTTOM (solid shape): 113.77,23.84 113.77,22.06 113.87,21.96 113.87,21.5 113.51,21.15 112.85,21.15 112.75,21.25 112.75,21.96 112.39,22.32 111.91,22.32 111.61,22.01 111.61,21.33 111.53,21.25 111.02,21.25 110.9,21.38 110.24,21.38 110.13,21.48 110.13,22.21 110.03,22.32 109.35,22.32 109.02,21.99 109.02,20.16 108.93,20.08 108.93,19.55 108.96,19.4 109.02,19.27 109.02,18.25 110.24,17.03 110.41,17.03 110.51,16.93 112.07,16.93 112.17,17.03 112.55,17.03 112.88,16.85 113.2,17.03 113.41,17.03 113.79,16.65 113.79,16.27 113.41,15.89 109.35,15.89 108.03,17.21 108.03,21.2 108.23,21.4 108.23,21.96 109.4,23.13 109.4,24.02 110.77,25.39 112.22,25.39
HSC_P12V_AGND on GND (solid shape): outline of 780 points within 103.91,16.93 118.57,29.86
HSC_P12V_AGND on VCC (solid shape): outline of 787 points within 103.91,16.93 118.57,29.86
HSC_P12V_AGND on GND1 (solid shape): outline of 285 points within 108.03,15.89 115.09,25.39
HSC_P12V_GATE on BOTTOM (solid shape): 101.09,82.06 101.09,81.17 100.97,81.04 100.97,38.37 103.31,36.02 106.36,36.02 109.22,33.16 109.22,27.27 109.96,26.53 109.96,26.25 109.75,26.05 108.61,26.05 108.6,26.06 107.3,26.06 107.06,26.3 107.06,31.89 105.22,33.73 102.55,33.73 98.55,37.73 98.55,76.6 98.57,76.61 98.55,76.61 98.55,81.12 99.59,82.16 100.99,82.16
HSC_P12V_STBY_AGND on TOP (solid shape): 102.58,4.12 102.79,4.08 103,4.12 103.02,4.13 103.17,4.13 103.56,3.75 103.56,2.61 103.17,2.22 101.9,2.22 101.79,2.34 101.78,2.35 101.78,4 101.9,4.13 102.57,4.13
HSC_P12V_STBY_AGND on GND (solid shape): outline of 401 points within 100.51,2.22 109.14,9.72
HSC_P12V_STBY_AGND on VCC (solid shape): outline of 401 points within 100.51,2.22 109.14,9.72
HSC_P12V_STBY_RSENSE on TOP (solid shape): 115.24,14.42 115.24,13.67 115.23,13.65 115.19,13.48 115.23,13.3 115.24,13.28 115.24,12.91 115.23,12.89 115.19,12.71 115.23,12.54 115.24,12.52 115.24,12.02 115.23,12 115.19,11.83 115.23,11.65 115.24,11.63 115.24,10.35 114.86,9.97 107.62,9.97 106.6,10.99 105.08,10.99 104.95,11.11 104.95,14.92 105.08,15.05 114.6,15.05
UNNAMED_14_BEAD_I89_1 on TOP (solid shape): 3.56,17.92 3.56,16.78 3.81,16.52 3.81,13.48 3.79,13.46 3.43,13.46 3.24,13.43 3.07,13.35 2.64,13.35 2.62,13.36 2.41,13.39 2.2,13.36 2.19,13.35 1.78,13.35 1.52,13.6 1.52,17.92 1.78,18.18 3.3,18.18
VR_P3V3_CB_PVIN on TOP (solid shape): outline of 94 points within 160.6,98.8 168.12,106.78
VR_P3V3_CB_PVIN on BOTTOM (solid shape): 166.19,107.9 166.19,107.11 166.47,106.83 166.47,104.74 167.26,103.95 168.1,103.95 168.4,103.65 168.4,100.24 167.37,99.21 164.49,99.21 164.34,99.37 164.34,100.61 163.78,101.17 162.13,101.17 161.85,100.89 161.85,100 161.54,99.7 161.21,99.7 160.58,100.33 160.58,102.39 165.81,102.39 165.81,102.33 165.83,102.28 165.85,102.23 165.87,102.18 165.91,102.13 165.95,102.09 165.99,102.06 166.04,102.04 166.09,102.02 166.15,102.01 166.21,102.01 166.26,102.01 166.31,102.03 166.37,102.05 166.41,102.08 166.46,102.11 166.49,102.15 166.52,102.2 166.55,102.25 166.56,102.31 166.57,102.36 166.57,102.42 166.56,102.47 166.55,102.52 166.52,102.58 166.49,102.62 166.46,102.66 166.41,102.7 166.37,102.73 166.31,102.75 166.26,102.76 166.21,102.77 166.15,102.77 166.09,102.76 166.04,102.74 165.99,102.71 165.95,102.68 165.91,102.64 165.87,102.6 165.85,102.55 165.83,102.5 165.81,102.44 165.81,102.39 160.58,102.39 160.58,102.74 160.93,103.1 162.27,103.1 162.9,103.73 162.9,106.44 163.22,106.76 164.03,106.76 165.25,107.98 166.11,107.98
VR_P3V3_CB_SW on TOP (solid shape): 164.92,109.22 164.92,108.9 165.01,108.81 168.37,108.81 168.37,107.19 165.73,107.19 164.97,106.43 164.97,105.28 164.82,105.13 160.44,105.13 160.27,105.3 160.27,109.11 160.46,109.3 164.84,109.3
VR_P3V3_STBY_PVIN on TOP (solid shape): 164.96,25.46 164.96,24.19 165.87,23.28 169.02,23.28 169.56,22.74 170.83,22.74 170.93,22.64 170.93,21.4 170.8,21.27 165.72,21.27 165.14,20.68 165.14,20.09 164.19,19.14 162.06,19.14 162.06,23.53 163.38,23.53 163.38,23.09 163.99,22.48 164.02,22.45 164.07,22.41 164.13,22.37 164.2,22.34 164.27,22.32 164.34,22.3 164.41,22.3 164.48,22.3 164.55,22.31 164.62,22.33 164.68,22.35 164.75,22.39 164.8,22.43 164.86,22.48 164.9,22.53 164.94,22.59 164.98,22.65 165,22.72 165.02,22.78 165.03,22.85 165.03,22.92 165.03,23 165.01,23.07 164.99,23.13 164.96,23.2 164.92,23.26 164.88,23.31 164.86,23.34 164.6,23.59 164.59,23.65 164.57,23.72 164.55,23.79 164.51,23.85 164.47,23.91 164.43,23.96 164.37,24.01 164.32,24.05 164.26,24.08 164.19,24.11 164.12,24.13 164.05,24.14 163.98,24.14 163.91,24.13 163.84,24.12 163.78,24.1 163.71,24.07 163.65,24.04 163.6,23.99 163.55,23.94 163.5,23.89 163.46,23.83 163.43,23.77 163.41,23.7 163.39,23.63 163.38,23.56 163.38,23.53 162.06,23.53 162.06,25.56 162.14,25.64 164.78,25.64
VR_P3V3_STBY_PVIN on BOTTOM (solid shape): 165.77,23.3 166.28,23.3 166.58,23 166.58,21.27 167.21,20.65 167.21,19.4 166.96,19.16 166.15,19.16 164.93,17.94 164.07,17.94 163.99,18.02 163.99,18.81 163.71,19.08 163.71,20.99 163.15,21.55 162.09,21.55 161.78,21.85 161.78,23.53 163.61,23.53 163.61,23.47 163.63,23.42 163.65,23.37 163.67,23.32 163.71,23.27 163.75,23.24 163.79,23.2 163.84,23.18 163.9,23.16 163.95,23.15 164.01,23.15 164.06,23.15 164.12,23.17 164.17,23.19 164.22,23.22 164.26,23.25 164.3,23.3 164.33,23.34 164.35,23.39 164.37,23.45 164.37,23.5 164.37,23.56 164.37,23.61 164.35,23.67 164.33,23.72 164.3,23.76 164.26,23.8 164.22,23.84 164.17,23.87 164.12,23.89 164.06,23.91 164.01,23.91 163.95,23.91 163.9,23.9 163.84,23.88 163.79,23.86 163.75,23.82 163.71,23.78 163.67,23.74 163.65,23.69 163.63,23.64 163.61,23.59 163.61,23.53 161.78,23.53 161.78,25.03 162.09,25.33 163.74,25.33
VR_P3V3_STBY_SW on TOP (solid shape): 167.87,19.22 167.87,16.07 167.73,15.93 165.64,15.93 165.26,16.32 165.26,17.01 165.17,17.1 161.82,17.1 161.82,18.73 164.45,18.73 165.01,19.29 167.8,19.29

Small or netless copper shapes (teardrops, artwork), in the pictures only: 3 on BOTTOM

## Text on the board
Ref Des/Silkscreen Top: HSC STATUS LED | HSC STBY LED | PSU1_MGMT | PSU1_PMBus | Riser5_GPU_PWR | Riser4_GPU_PWR | Riser3_GPU_PWR | Riser3_PWR | Riser4_2X6_PWR | Riser5_PWR | 2X2_PWR | Riser4 | LED_Conn | PSU2_MGMT | D | PSU2_PMBus | PSU3_PMBus | B | E | C | A | Cerberus_PWR | FAN_PWR | MB | PSU3 | PSU2 | PSU1 | PCB-PDBMOXL6-P1
User.14: 3
User.15: 4
User.20: FIGURE | SIZE | 10.0 | 22.0 | 36.0 | 41.0 | 43.0 | 57.0 | 73.0 | 221.0 | 40.0 | 120.0 | 121.0 | 158.0 | 99.0x32.0 | DRILL CHART: TOP to BOTTOM | ALL UNITS ARE IN MILS | TOLERANCE | +3.0/-3.0 | +4.0/-0.0 | +2.0/-2.0 | +4.0/-4.0 | PLATED | NON-PLATED | QTY | 140 | 1499 | 10 | 25 | 94 | 1 | 100 | 80 | 24 | 2 | 7 | 16 | 5
